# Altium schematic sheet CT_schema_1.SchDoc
size 642 x 258 mm
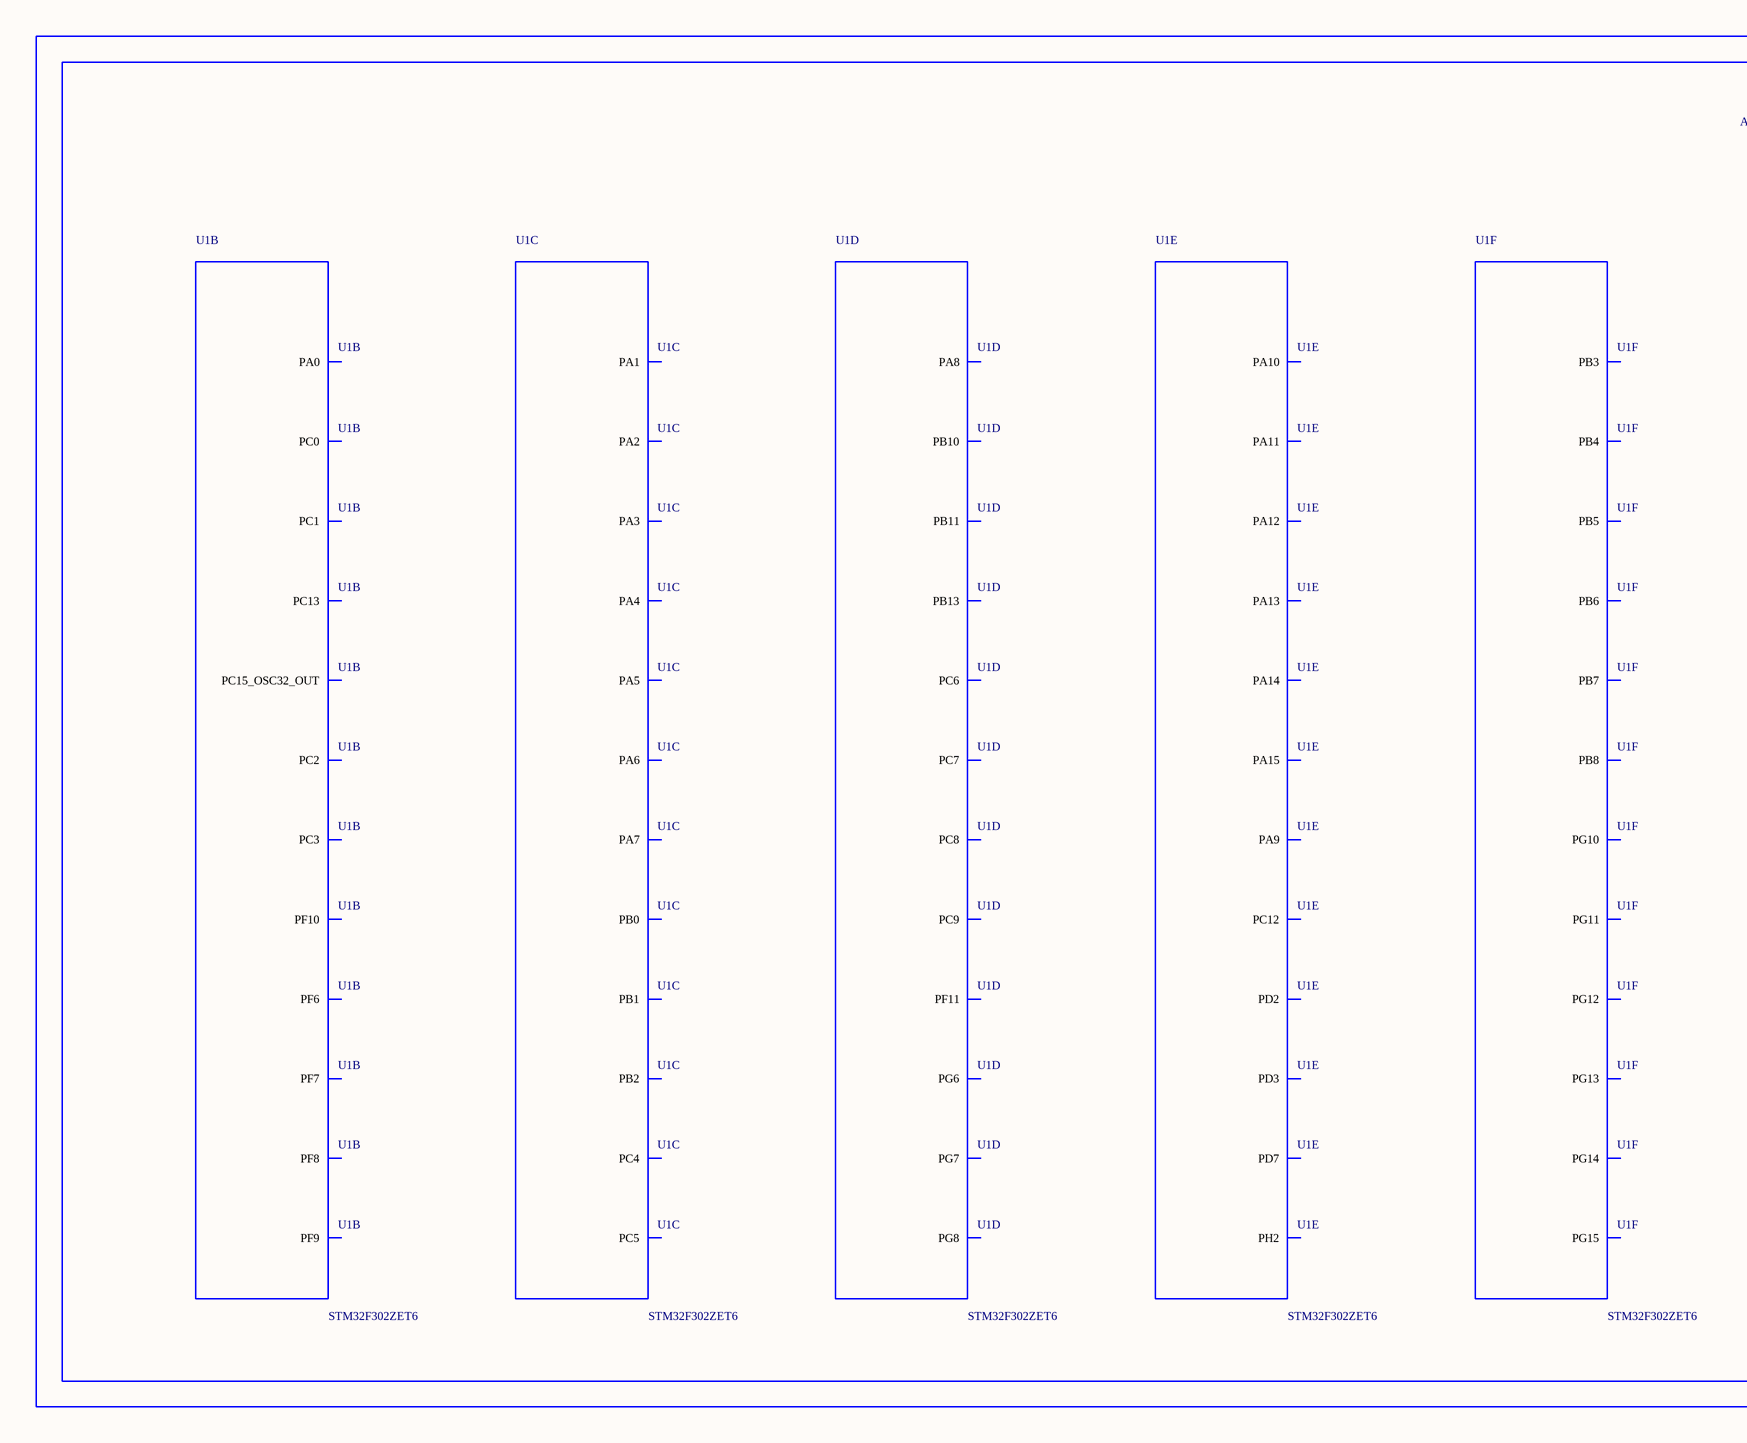
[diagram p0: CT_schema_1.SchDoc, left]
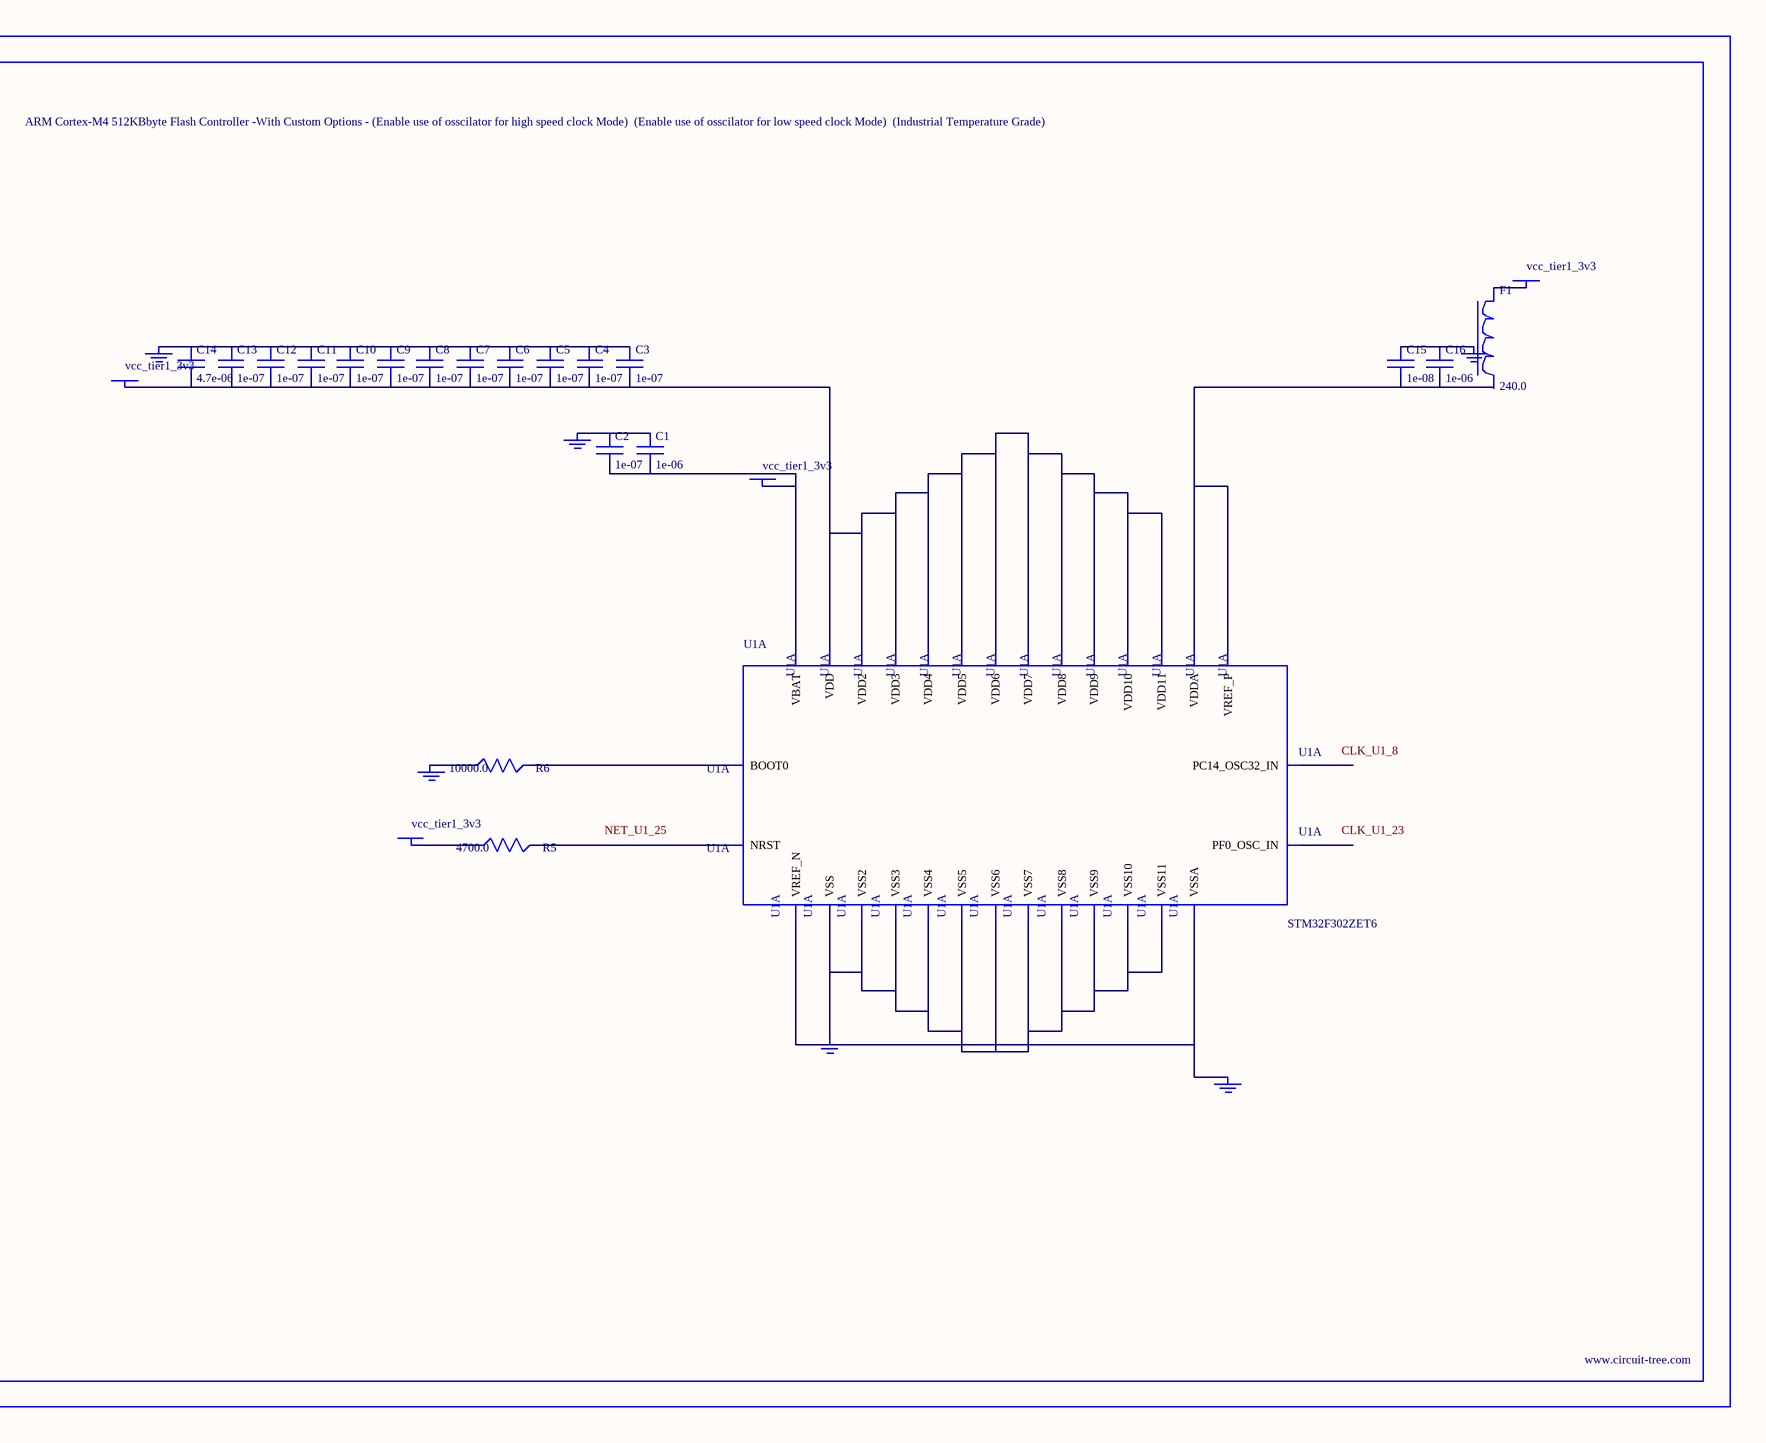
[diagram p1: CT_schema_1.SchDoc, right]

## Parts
BORDER0  (no value)
C1  1e-06  [C0603]
C2  1e-07  [C0603]
C3  1e-07  [C0603]
C4  1e-07  [C0603]
C5  1e-07  [C0603]
C6  1e-07  [C0603]
C7  1e-07  [C0603]
C8  1e-07  [C0603]
C9  1e-07  [C0603]
C10  1e-07  [C0603]
C11  1e-07  [C0603]
C12  1e-07  [C0603]
C13  1e-07  [C0603]
C14  4.7e-06  [C0603]
C15  1e-08  [C0603]
C16  1e-06  [C0603]
F1  240.0  [L0603]
GND_INSTANCE_0_0  (no value)
GND_INSTANCE_0_1  (no value)
GND_INSTANCE_0_2  (no value)
GND_INSTANCE_0_3  (no value)
GND_INSTANCE_0_4  (no value)
GND_INSTANCE_0_5  (no value)
POWER_INSTANCE_0_0  vcc_tier1_3v3
POWER_INSTANCE_0_1  vcc_tier1_3v3
POWER_INSTANCE_0_2  vcc_tier1_3v3
POWER_INSTANCE_0_3  vcc_tier1_3v3
R5  4700.0  [R0603]
R6  10000.0  [R0603]
U1  STM32F302ZET6  [LQFP144]  (parts A,B,C,D,E,F of 12)

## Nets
NetC1_1: C1.1 C2.1 GND_INSTANCE_0_0.0(GND)
NetC1_2: C1.2 C2.2 POWER_INSTANCE_0_0.0(PWR) U1.6(VBAT)
NetC3_1: C3.1 C4.1 C5.1 C6.1 C7.1 C8.1 C9.1 C10.1 C11.1 C12.1 C13.1 C14.1 GND_INSTANCE_0_1.0(GND)
NetC3_2: C3.2 C4.2 C5.2 C6.2 C7.2 C8.2 C9.2 C10.2 C11.2 C12.2 C13.2 C14.2 POWER_INSTANCE_0_1.0(PWR) U1.17(VDD) U1.39(VDD2) U1.52(VDD3) U1.62(VDD4) U1.72(VDD5) U1.84(VDD6) U1.95(VDD7) U1.108(VDD8) U1.121(VDD9) U1.131(VDD10) U1.144(VDD11)
NetC15_1: C15.1 C16.1 GND_INSTANCE_0_3.0(GND)
NetC15_2: C15.2 C16.2 U1.32(VREF_P) U1.33(VDDA)
NetF1_1: F1.1 POWER_INSTANCE_0_2.0(PWR)
NetGND_INSTANCE_0_2_0: GND_INSTANCE_0_2.0(GND) U1.30(VSSA) U1.31(VREF_N)
NetGND_INSTANCE_0_4_0: GND_INSTANCE_0_4.0(GND) R6.1
NetGND_INSTANCE_0_5_0: GND_INSTANCE_0_5.0(GND) U1.16(VSS) U1.38(VSS2) U1.51(VSS3) U1.61(VSS4) U1.71(VSS5) U1.83(VSS6) U1.94(VSS7) U1.107(VSS8) U1.120(VSS9) U1.130(VSS10) U1.143(VSS11)
NetPOWER_INSTANCE_0_3_0: POWER_INSTANCE_0_3.0(PWR) R5.1
NetR5_2: R5.2 U1.25(NRST)
NetR6_2: R6.2 U1.138(BOOT0)

Not connected (* = marked no-connect by the designer): F1 2; U1 7(PC13) 8(PC14_OSC32_IN) 9(PC15_OSC32_OUT) 18(PF6) 19(PF7) 20(PF8) 21(PF9) 22(PF10) 23(PF0_OSC_IN) 26(PC0) 27(PC1) 28(PC2) 29(PC3) 34(PA0) 35(PA1) 36(PA2) 37(PA3) 40(PA4) 41(PA5) 42(PA6) 43(PA7) 44(PC4) 45(PC5) 46(PB0) 47(PB1) 48(PB2) 49(PF11) 69(PB10) 70(PB11) 74(PB13) 91(PG6) 92(PG7) 93(PG8) 96(PC6) 97(PC7) 98(PC8) 99(PC9) 100(PA8) 101(PA9) 102(PA10) 103(PA11) 104(PA12) 105(PA13) 106(PH2) 109(PA14) 110(PA15) 113(PC12) 116(PD2) 117(PD3) 123(PD7) 125(PG10) 126(PG11) 127(PG12) 128(PG13) 129(PG14) 132(PG15) 133(PB3) 134(PB4) 135(PB5) 136(PB6) 137(PB7) 139(PB8)

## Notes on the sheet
- Labels drawn without touching a wire or pin: CLK_U1_8, CLK_U1_23, NET_U1_25

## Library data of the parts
BORDER0 = BORDER_PAGE0
C1 C16 = C0603C105K3RACTU
C2-C13 = 06035C104K4Z2A
C14 = GRM188R6YA475KE15D
C15 = 06035C103K4Z2A
F1 = Z0603C241ASMST
GND_INSTANCE_0_0-GND_INSTANCE_0_5 = GND
POWER_INSTANCE_0_0-POWER_INSTANCE_0_3 = PWR
R5 = RC0603JR-074K7L
R6 = RC0603JR-0710KL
